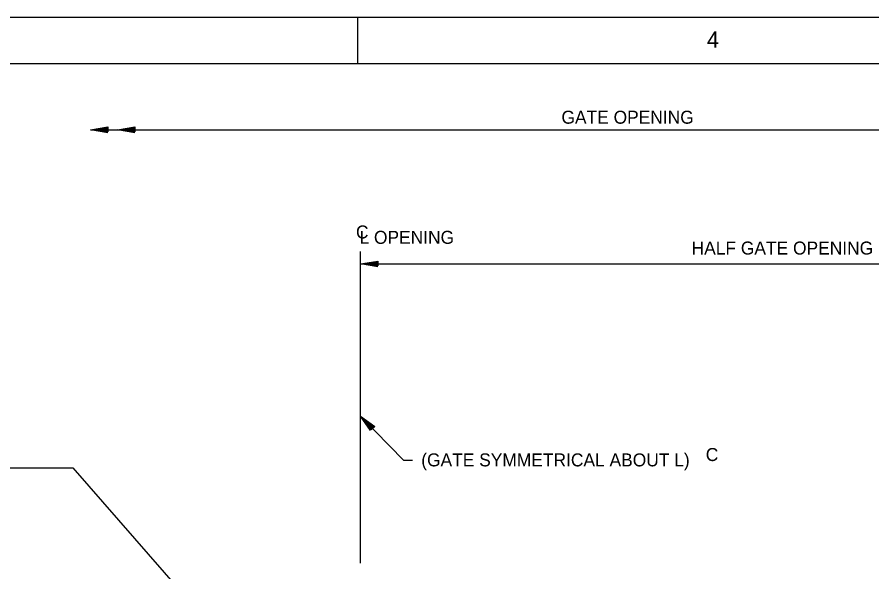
# Model space of a CAD drawing. Extents: x 0.1 to 13.5, y 0.1 to 9.5.
# Drawn here: x 1.9 to 4.972, y 7.464 to 9.458 of the extents above; entities that cross this region are included whole.
import ezdxf

# ---------------------------------------------------------------- set-up
doc = ezdxf.new("R2010")
doc.units = 0
for name, color, linetype in [('Level 1', 7, 'Continuous'), ('Level 25', 7, 'Continuous'), ('Level 3', 7, 'Continuous'), ('Level 50', 7, 'Continuous')]:
    doc.layers.add(name, color=color, linetype=linetype)

msp = doc.modelspace()

# ---------------------------------------------------------------- linework, layer by layer
at = {"layer": 'Level 1'}
msp.add_line((3.125, 9.2917), (3.125, 9.4583), dxfattribs=at)
for points in [[(0.125, 9.4583), (13.4583, 9.4583), (13.4583, 0.125), (0.125, 0.125)], [(0.625, 9.2917), (13.2917, 9.2917), (13.2917, 0.2917), (0.625, 0.2917)]]:
    msp.add_lwpolyline(points, close=True, dxfattribs=at)
at = {"layer": 'Level 25'}
for p, q in [((2.1636, 9.053), (6.3151, 9.053)), ((3.1347, 7.4962), (3.1347, 8.616)), ((3.1347, 8.5712), (6.3151, 8.5712))]:
    msp.add_line(p, q, dxfattribs=at)
at = {"layer": 'Level 3'}
for points in [[(3.3209, 7.8644), (3.2896, 7.8644), (3.1347, 8.0241)], [(1.7783, 7.8386), (2.1006, 7.8386), (2.8149, 7.0196)]]:
    msp.add_lwpolyline(points, dxfattribs=at)
at = {"layer": 'Level 50'}
for p, q in [((2.3233, 9.0634), (2.3233, 9.0634)), ((2.1636, 9.053), (2.1636, 9.053)), ((2.1809, 9.053), (2.1809, 9.053)), ((2.3123, 9.053), (2.3123, 9.053)), ((2.3179, 9.0567), (2.3179, 9.0567)), ((2.3179, 9.052), (2.3179, 9.052)), ((2.3206, 9.06), (2.3206, 9.06)), ((2.3206, 9.0487), (2.3206, 9.0487)), ((2.3233, 9.0457), (2.3233, 9.0457)), ((2.3233, 9.0427), (2.3233, 9.0427)), ((3.1347, 8.5712), (3.1347, 8.5712)), ((3.152, 8.5712), (3.152, 8.5712)), ((3.1347, 8.0241), (3.1347, 8.0241)), ((3.1468, 8.0117), (3.1468, 8.0117))]:
    msp.add_line(p, q, dxfattribs=at)
for points in [[(2.2259, 9.0427), (2.1636, 9.053), (2.2259, 9.0634), (2.2259, 9.0457), (2.1809, 9.053), (2.2233, 9.06), (2.2233, 9.0487), (2.1976, 9.053), (2.2206, 9.0567), (2.2206, 9.052), (2.2149, 9.053)], [(2.3233, 9.0427), (2.2609, 9.053), (2.3233, 9.0634), (2.3233, 9.0457), (2.2783, 9.053), (2.3206, 9.06), (2.3206, 9.0487), (2.2949, 9.053), (2.3179, 9.0567), (2.3179, 9.052), (2.3123, 9.053)], [(3.197, 8.5608), (3.1347, 8.5712), (3.197, 8.5815), (3.197, 8.5638), (3.152, 8.5712), (3.1944, 8.5782), (3.1944, 8.5668), (3.1687, 8.5712), (3.1917, 8.5748), (3.1917, 8.5702), (3.186, 8.5712)], [(3.1707, 7.9722), (3.1347, 8.0241), (3.1855, 7.9866), (3.1728, 7.9743), (3.1468, 8.0117), (3.1813, 7.9862), (3.1731, 7.9783), (3.1584, 7.9997), (3.177, 7.9858), (3.1737, 7.9825), (3.1704, 7.9873)]]:
    msp.add_lwpolyline(points, dxfattribs=at)

# ---------------------------------------------------------------- texts
at = {"layer": 'Level 1'}
for s, height, p in [('4', 0.0584, (4.3789, 9.3482)), ('GATE OPENING', 0.046698, (3.8563, 9.0751)), ('C', 0.0467, (3.1179, 8.6627)), ('L OPENING', 0.0467, (3.1305, 8.6434)), ('HALF GATE OPENING', 0.046698, (4.324, 8.6049)), ('C', 0.0467, (4.3748, 7.8627)), ('(GATE SYMMETRICAL ABOUT L)', 0.046698, (3.3525, 7.8435))]:
    msp.add_text(s, height=height, dxfattribs=at).set_placement(p)

doc.saveas('drawing.dxf')
